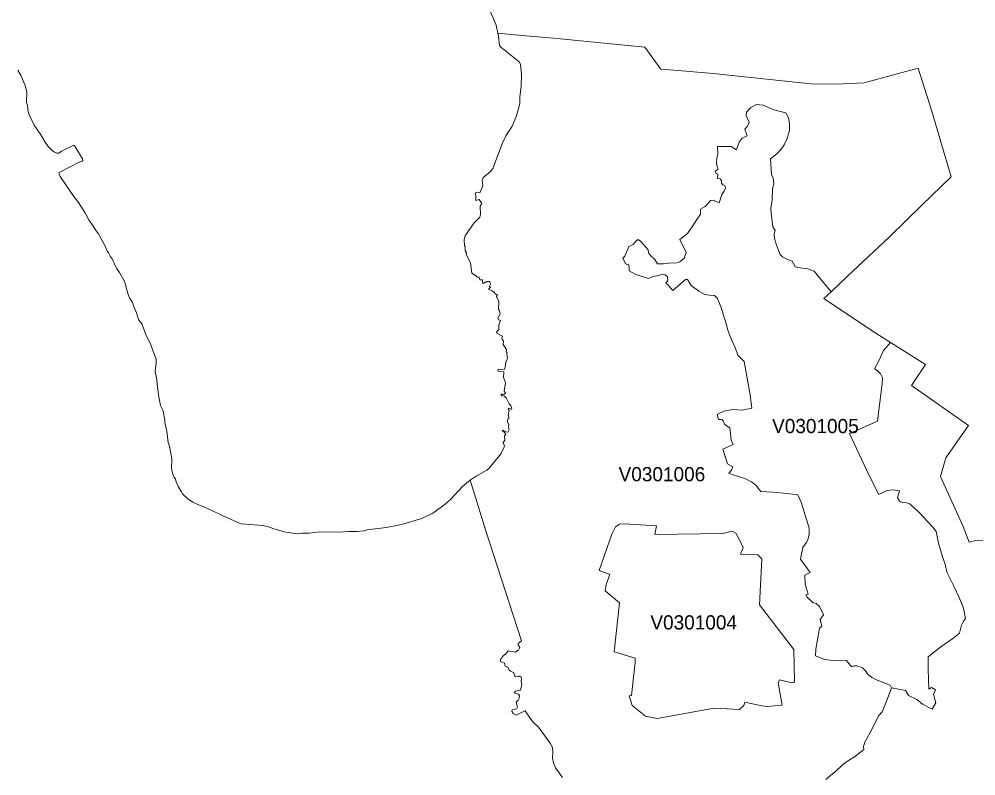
# Model space of a CAD drawing. Extents: x 369010 to 735936, y 6377141 to 6616555.
# Drawn here: x 386574 to 393307, y 6474944 to 6480269 of the extents above; entities that cross this region are included whole.
import ezdxf
from ezdxf.enums import TextEntityAlignment as Align

# ---------------------------------------------------------------- set-up
doc = ezdxf.new("R2010")
doc.units = 0
doc.header["$LTSCALE"] = 40
doc.layers.add('3', color=7, linetype='Continuous', lineweight=13)
doc.layers.add('4', color=7, linetype='Continuous')

msp = doc.modelspace()

# ---------------------------------------------------------------- linework, layer by layer
at = {"layer": '3'}
for points in [[(389891.85, 6480320.15), (389931.24, 6480224.99), (389943.15, 6480170.37)], [(391869.12, 6479176.02), (391880.87, 6479150.37), (391886.17, 6479106.84), (391876.9, 6479076.56), (391874.42, 6478996.29), (391865.15, 6478937.04), (391866.47, 6478905.42), (391878.22, 6478806.78), (391894.11, 6478780.47), (391888.49, 6478754.98), (391891.13, 6478724.69), (391904.37, 6478678.68), (391929.37, 6478612.81), (391946.41, 6478597.09), (391982, 6478577.23), (392014.77, 6478565.48), (392022.71, 6478548.27), (392035.78, 6478527.25), (392053, 6478521.95), (392124, 6478511.52), (392168.68, 6478494.31), (392188.54, 6478472.8), (392288.51, 6478350.82), (392402.05, 6478456.91), (392698.63, 6478737.44), (392926.36, 6478958.72), (393134.4, 6479159.8), (392995.38, 6479628.35), (392900.71, 6479924.6), (392788.99, 6479891.99), (392521.37, 6479819.34), (392325.91, 6479809.9), (392148.33, 6479812.72), (391678.13, 6479863.03), (391460, 6479886.37), (391182.61, 6479910.36), (391088.94, 6479917.15), (390978.21, 6480072.39), (390524.73, 6480116.75), (390410.04, 6480128.5), (390333.91, 6480135.45), (390140.76, 6480150.01), (390037.16, 6480161.1), (389943.15, 6480170.37), (389947.95, 6480147.7), (389953.58, 6480083.15), (389962.85, 6480071.57), (390092.6, 6479968.79), (390102.86, 6479951.08), (390110.48, 6479879.75), (390107.83, 6479796.5), (390096.57, 6479720.2), (390098.56, 6479674.36), (390074.4, 6479587.3), (390044.11, 6479514.64), (389999.09, 6479447.12), (389972.78, 6479391.18), (389907.73, 6479217.56), (389889.86, 6479194.06), (389840.04, 6479154.18), (389832.76, 6479134.32), (389836.73, 6479094.76), (389816.87, 6479047.43), (389800.16, 6479051.4), (389782.61, 6479045.11), (389788.24, 6479028.06), (389788.24, 6478993.64), (389810.75, 6478998.6), (389830.78, 6478971.63), (389818.86, 6478953.42), (389821.18, 6478894), (389815.22, 6478876.13), (389775.33, 6478836.57), (389712.94, 6478744.06), (389705.65, 6478717.74), (389707.97, 6478672.73), (389713.27, 6478669.25), (389712.61, 6478638.47), (389723.2, 6478623.24), (389719.56, 6478612.65), (389751.5, 6478553.89), (389760.77, 6478480.41), (389791.55, 6478460.88), (389795.85, 6478453.27), (389811.91, 6478452.6), (389817.2, 6478434.07), (389833.75, 6478435.06), (389835.74, 6478414.04), (389842.36, 6478407.75), (389852.95, 6478418.01), (389863.21, 6478417.02), (389867.52, 6478423.64), (389886.88, 6478422.81), (389890.19, 6478402.79), (389885.23, 6478389.88), (389891.18, 6478381.6), (389878.94, 6478373.66), (389877.94, 6478367.7), (389902.11, 6478357.94), (389911.71, 6478348.01)], [(389943.15, 6480170.37), (390037.16, 6480161.1), (390140.76, 6480150.01), (390333.91, 6480135.45), (390410.04, 6480128.5), (390524.73, 6480116.75), (390978.21, 6480072.39), (391088.94, 6479917.15), (391182.61, 6479910.36), (391460, 6479886.37), (391678.13, 6479863.03), (392148.33, 6479812.72), (392325.91, 6479809.9), (392521.37, 6479819.34), (392788.99, 6479891.99), (392900.71, 6479924.6), (392995.38, 6479628.35), (393134.4, 6479159.8), (392926.36, 6478958.72), (392698.63, 6478737.44), (392402.05, 6478456.91), (392288.51, 6478350.82), (392236.38, 6478302.16), (392576.65, 6478075.59), (392705.74, 6477994.49), (392888.46, 6477879.63), (392952.01, 6477838.42), (392854.53, 6477689.8), (393256.54, 6477409.1), (393095.67, 6477183.19), (393059.59, 6477049.79), (393217.98, 6476700.08), (393261.01, 6476588.2), (393307.02, 6476599.95), (393819.92, 6476581.75)], [(387041.37, 6478899.96), (386991.06, 6478978.41), (386958.78, 6479020.12), (386861.3, 6479162.45), (386852.53, 6479184.13), (386854.52, 6479188.44), (386999.99, 6479265.06), (387017.87, 6479269.04), (387020.85, 6479273.34), (387019.19, 6479285.42), (386965.74, 6479374.96), (386960.44, 6479380.25), (386954.15, 6479380.25), (386871.89, 6479338.71), (386853.19, 6479325.47), (386837.97, 6479326.47), (386823.07, 6479333.75), (386801.89, 6479349.14), (386777.23, 6479372.64), (386757.53, 6479401.94), (386726.75, 6479455.23), (386679.41, 6479523.25), (386650.12, 6479581.84), (386641.51, 6479603.35), (386637.87, 6479619.74), (386632.91, 6479661.78), (386626.95, 6479674.69), (386625.29, 6479682.96), (386628.27, 6479758.27), (386616.69, 6479801.79), (386585.08, 6479874.45), (386565.22, 6479910.7)], [(391631.46, 6477904.62), (391615.57, 6477950.63), (391578.83, 6478034.87), (391559.13, 6478086.18), (391553.18, 6478116.8), (391536.13, 6478169.43), (391516.27, 6478233.81), (391488.79, 6478303.65), (391467.61, 6478324.67), (391429.54, 6478327.32), (391393.96, 6478333.94), (391357.22, 6478354.96), (391303.26, 6478394.51), (391276.95, 6478436.55), (391262.55, 6478436.55), (391174.5, 6478360.25), (391125.68, 6478415.53), (391140.24, 6478427.28), (391137.76, 6478454.43), (391120.71, 6478470.31), (391103.5, 6478474.29), (391073.38, 6478465.02), (391036.47, 6478458.4), (390999.73, 6478444), (390910.19, 6478474.29), (390866.83, 6478497.95), (390868.15, 6478520.3), (390865.51, 6478539.99), (390841.84, 6478546.61), (390822.14, 6478587.49), (390836.54, 6478601.89), (390865.51, 6478669.08), (390895.79, 6478682.16), (390918.14, 6478711.12), (390931.21, 6478717.74), (390947.93, 6478705.83), (391000.56, 6478646.58), (391003.21, 6478624.23), (391017.6, 6478604.54), (391047.89, 6478578.06), (391067.59, 6478547.94), (391108.47, 6478547.94), (391163.58, 6478554.39), (391192.54, 6478551.74), (391222.83, 6478561.01), (391254.44, 6478587.33), (391267.52, 6478625.56), (391222.83, 6478717.58), (391278.11, 6478761.1), (391316.17, 6478815.06), (391343.81, 6478858.42), (391370.13, 6478896.65), (391370.13, 6478930.91), (391401.57, 6478949.28), (391416.97, 6478965.34), (391439.31, 6478991.65), (391461.65, 6478994.3), (391501.04, 6478975.93), (391519.41, 6479033.85), (391536.62, 6479057.52), (391545.73, 6479079.87), (391540.43, 6479097.08), (391527.36, 6479102.21), (391516.76, 6479114.12), (391518.09, 6479132.5), (391507.66, 6479145.74), (391487.97, 6479147.06), (391490.45, 6479177.35), (391476.05, 6479185.13), (391473.4, 6479198.37), (391493.1, 6479212.43), (391486.48, 6479232.13), (391482.5, 6479258.44), (391485.15, 6479290.06), (391490.45, 6479321.67), (391489.13, 6479371.65), (391585.12, 6479372.97), (391623.18, 6479347.98), (391641.55, 6479401.94), (391662.74, 6479432.22), (391698.16, 6479447.95), (391681.11, 6479494.12), (391699.48, 6479516.46), (391712.72, 6479544.1), (391690.21, 6479587.47), (391692.86, 6479613.78), (391720.5, 6479644.07), (391762.54, 6479669.06), (391810.04, 6479662.6), (391884.85, 6479630.99), (391969.09, 6479609.97), (391987.46, 6479573.07), (391995.4, 6479534.84), (391995.4, 6479482.21), (391975.71, 6479424.28), (391958.49, 6479384.89), (391936.15, 6479354.6), (391907.35, 6479320.84), (391862.67, 6479285.26), (391869.12, 6479176.02)], [(393144.83, 6475910.13), (393191.83, 6475948.03), (393206.23, 6476005.63), (393217.98, 6476029.3), (393233.7, 6476051.47), (393221.95, 6476113.04), (393216.66, 6476136.54), (393190.84, 6476198.94), (393155.58, 6476274.74), (393103.29, 6476378.18), (393090.21, 6476433.13), (393071.84, 6476485.42), (393044.37, 6476580.92), (393028.48, 6476663.01), (393004.81, 6476694.62), (392908.65, 6476797.23), (392841.62, 6476859.13), (392822.09, 6476866.41), (392789.32, 6476867.74), (392772.11, 6476874.36), (392756.39, 6476900.67), (392770.79, 6476949.33), (392726.1, 6476957.28), (392681.42, 6476951.98), (392623.65, 6476923.02), (392555.14, 6477062.54), (392418.6, 6477354.15), (392614.55, 6477439.72), (392648.98, 6477706.18), (392650.3, 6477744.25), (392635.74, 6477773.21), (392612.07, 6477796.88), (392595.02, 6477807.47), (392627.96, 6477874.66), (392656.92, 6477937.39), (392705.74, 6477994.49), (392576.65, 6478075.59), (392236.38, 6478302.16), (392288.51, 6478350.82), (392188.54, 6478472.8), (392168.68, 6478494.31), (392124, 6478511.52), (392053, 6478521.95), (392035.78, 6478527.25), (392022.71, 6478548.27), (392014.77, 6478565.48), (391982, 6478577.23), (391946.41, 6478597.09), (391929.37, 6478612.81), (391904.37, 6478678.68), (391891.13, 6478724.69), (391888.49, 6478754.98), (391894.11, 6478780.47), (391878.22, 6478806.78), (391866.47, 6478905.42), (391865.15, 6478937.04), (391874.42, 6478996.29), (391876.9, 6479076.56), (391886.17, 6479106.84), (391880.87, 6479150.37), (391869.12, 6479176.02), (391862.67, 6479285.26), (391907.35, 6479320.84), (391936.15, 6479354.6), (391958.49, 6479384.89), (391975.71, 6479424.28), (391995.4, 6479482.21), (391995.4, 6479534.84), (391987.46, 6479573.07), (391969.09, 6479609.97), (391884.85, 6479630.99), (391810.04, 6479662.6), (391762.54, 6479669.06), (391720.5, 6479644.07), (391692.86, 6479613.78), (391690.21, 6479587.47), (391712.72, 6479544.1), (391699.48, 6479516.46), (391681.11, 6479494.12), (391698.16, 6479447.95), (391662.74, 6479432.22), (391641.55, 6479401.94), (391623.18, 6479347.98), (391585.12, 6479372.97), (391489.13, 6479371.65), (391490.45, 6479321.67), (391485.15, 6479290.06), (391482.5, 6479258.44), (391486.48, 6479232.13), (391493.1, 6479212.43), (391473.4, 6479198.37), (391476.05, 6479185.13), (391490.45, 6479177.35), (391487.97, 6479147.06), (391507.66, 6479145.74), (391518.09, 6479132.5), (391516.76, 6479114.12), (391527.36, 6479102.21), (391540.43, 6479097.08), (391545.73, 6479079.87)], [(391545.73, 6479079.87), (391536.62, 6479057.52), (391519.41, 6479033.85), (391501.04, 6478975.93), (391461.65, 6478994.3), (391439.31, 6478991.65), (391416.97, 6478965.34), (391401.57, 6478949.28), (391370.13, 6478930.91), (391370.13, 6478896.65), (391343.81, 6478858.42), (391316.17, 6478815.06), (391278.11, 6478761.1), (391222.83, 6478717.58), (391267.52, 6478625.56), (391254.44, 6478587.33), (391222.83, 6478561.01), (391192.54, 6478551.74), (391163.58, 6478554.39), (391108.47, 6478547.94), (391067.59, 6478547.94), (391047.89, 6478578.06), (391017.6, 6478604.54), (391003.21, 6478624.23), (391000.56, 6478646.58), (390947.93, 6478705.83), (390931.21, 6478717.74), (390918.14, 6478711.12), (390895.79, 6478682.16), (390865.51, 6478669.08), (390836.54, 6478601.89), (390822.14, 6478587.49), (390841.84, 6478546.61), (390865.51, 6478539.99), (390868.15, 6478520.3), (390866.83, 6478497.95), (390910.19, 6478474.29), (390999.73, 6478444), (391036.47, 6478458.4), (391073.38, 6478465.02)], [(390096.74, 6475847.24), (390086.31, 6475865.61), (390086.31, 6475874.71), (390108.49, 6475894.41), (389857.75, 6476668.47), (389748.02, 6477024.64), (389735.78, 6477016.2), (389695.06, 6476979.62), (389611.98, 6476891.41), (389568.95, 6476854.17), (389484.54, 6476792.1), (389407.91, 6476754.86), (389265.25, 6476711.83), (389156.02, 6476692.14), (389022.12, 6476676.09), (388999.61, 6476668.8), (388954.1, 6476664.67), (388892.86, 6476663.51), (388821.86, 6476658.05), (388685.98, 6476660.53), (388615.15, 6476652.09), (388563.35, 6476650.93), (388531.57, 6476647.29), (388451.8, 6476659.2), (388367.22, 6476682.71), (388328, 6476697.6), (388289.6, 6476706.7), (388137.34, 6476716.8), (388086.86, 6476737.65), (388035.88, 6476762.64), (388006.92, 6476774.56), (387977.79, 6476790.45), (387952.8, 6476800.71), (387934.26, 6476809.32), (387868.89, 6476838.61), (387847.04, 6476845.56), (387796.23, 6476870.06), (387762.31, 6476891.41), (387724.41, 6476929.14), (387715.8, 6476943.04), (387694.28, 6476975.98), (387691.64, 6476989.22), (387679.06, 6477011.4), (387673.1, 6477033.24), (387664.66, 6477044.83), (387657.05, 6477061.21), (387648.44, 6477095.14), (387646.45, 6477108.71), (387647.45, 6477171.44), (387641.82, 6477217.61), (387629.24, 6477270.41), (387622.62, 6477290.27), (387613.35, 6477369.55), (387600.11, 6477429.62), (387598.62, 6477450.31), (387597.63, 6477455.94), (387591.01, 6477485.73), (387588.69, 6477503.44), (387583.07, 6477521.31), (387567.84, 6477551.1), (387559.89, 6477599.27), (387557.58, 6477612.51), (387554.76, 6477625.58), (387539.37, 6477743.92), (387530.6, 6477788.77), (387531.59, 6477794.06), (387538.05, 6477847.52), (387537.22, 6477871.19), (387534.9, 6477883.11), (387514.71, 6477936.56), (387499.15, 6477984.23), (387468.7, 6478043.15), (387438.75, 6478120.11), (387431.79, 6478132.69), (387426.17, 6478137.98), (387414.58, 6478155.86), (387399.52, 6478201.37), (387378.01, 6478252.18), (387370.39, 6478274.03), (387352.35, 6478302.99), (387343.08, 6478324.84), (387338.78, 6478339.4), (387337.46, 6478343.37), (387326.53, 6478378.96), (387321.24, 6478402.79), (387309.98, 6478432.41), (387280.03, 6478485.54), (387259.5, 6478516.99), (387255.2, 6478524.93), (387228.22, 6478581.37), (387214.98, 6478601.56), (387203.4, 6478623.57), (387194.13, 6478636.48), (387177.91, 6478670.74), (387131.07, 6478758.62), (387123.46, 6478768.88), (387110.22, 6478785.1), (387094.17, 6478813.07), (387065.04, 6478856.6), (387041.37, 6478899.96)], [(391073.38, 6478465.02), (391103.5, 6478474.29), (391120.71, 6478470.31), (391137.76, 6478454.43), (391140.24, 6478427.28), (391125.68, 6478415.53), (391174.5, 6478360.25), (391262.55, 6478436.55), (391276.95, 6478436.55), (391303.26, 6478394.51), (391357.22, 6478354.96), (391393.96, 6478333.94), (391429.54, 6478327.32), (391467.61, 6478324.67), (391488.79, 6478303.65), (391516.27, 6478233.81), (391536.13, 6478169.43), (391553.18, 6478116.8), (391559.13, 6478086.18), (391578.83, 6478034.87), (391615.57, 6477950.63), (391631.46, 6477904.62), (391677.47, 6477859.77), (391719.51, 6477624.26), (391731.26, 6477531.08), (391661.58, 6477518), (391595.88, 6477521.98), (391532.82, 6477511.38), (391485.48, 6477486.39), (391495.91, 6477452.46), (391518.25, 6477452.46), (391528.85, 6477442.04), (391539.27, 6477418.37), (391551.19, 6477406.45), (391576.18, 6477393.21), (391584.12, 6477305.17), (391599.85, 6477276.2), (391527.52, 6477243.27), (391559.13, 6477140.16), (391595.88, 6477119.14), (391586.77, 6477095.47), (391569.56, 6477074.45), (391591.9, 6477063.86), (391681.44, 6477037.55), (391728.77, 6477013.88), (391757.57, 6476990.21), (391793.16, 6476945.36), (391878.56, 6476941.39), (391978.52, 6476930.96), (392053.49, 6476921.69), (392077.16, 6476869.06), (392133.43, 6476687.84), (392133.43, 6476645.8), (392123.67, 6476604.42), (392117.21, 6476590.02), (392088.42, 6476550.8), (392072.69, 6476469.87), (392140.71, 6476375.7), (392104.14, 6476356.17), (392105.46, 6476293.27), (392127.64, 6476223.93), (392110.59, 6476217.47), (392120.85, 6476202.25), (392161.24, 6476163.02), (392182.26, 6476157.73), (392205.76, 6476136.87), (392235.88, 6476076.63), (392212.38, 6476044.03), (392224.13, 6475995.53), (392205.76, 6475983.78), (392180.93, 6475835.99), (392179.61, 6475789.15), (392242.33, 6475763), (392323.43, 6475753.73), (392397.91, 6475755.06), (392422.73, 6475723.94), (392437.13, 6475710.87), (392450.21, 6475717.49), (392468.58, 6475717.49), (392510.45, 6475704.41), (392526.01, 6475688.69), (392548.35, 6475657.24), (392574.5, 6475636.39), (392613.56, 6475617.02), (392705.08, 6475583.1), (392712.86, 6475564.73), (392812.99, 6475546.19), (392834.01, 6475510.77), (392892.76, 6475481.97), (392931.99, 6475448.05), (393000.01, 6475412.79), (393024.84, 6475457.15), (393009.11, 6475516.07), (393022.19, 6475550.16), (392996.04, 6475567.04), (392976.51, 6475555.29), (392971.21, 6475694.65), (392971.21, 6475782.36), (393060.09, 6475851.71), (393144.83, 6475910.13)], [(389911.71, 6478348.01), (389917.66, 6478349), (389921.97, 6478337.41), (389941.33, 6478326.49), (389932.56, 6478317.88), (389948.94, 6478281.31), (389946.63, 6478229.17), (389955.57, 6478215.93), (389958.21, 6478195.08), (389943.32, 6478163.8), (389946.3, 6478152.88), (389961.85, 6478147.25), (389948.94, 6478116.8), (389950.27, 6478087.17), (389934.55, 6478065.33), (389934.88, 6478058.04), (389975.43, 6478039.01), (389971.45, 6478019.81), (389983.04, 6478003.92), (389980.72, 6477978.6), (390004.06, 6477944.51), (390002.57, 6477928.95), (390007.37, 6477917.53), (390006.54, 6477907.6), (390010.35, 6477891.05), (390008.53, 6477876.49), (389997.93, 6477854.31), (389995.12, 6477821.7), (389988.67, 6477802.67), (389946.13, 6477805.32), (389941.83, 6477799.03), (389944.15, 6477792.41), (389984.2, 6477786.12), (389983.04, 6477747.39), (389996.61, 6477710.15), (389986.68, 6477651.4), (389995.95, 6477636.84), (389982.38, 6477625.58), (389968.47, 6477632.53), (389963.84, 6477629.55), (389971.12, 6477617.47), (389989.66, 6477614.82), (390001.08, 6477603.9), (390021.6, 6477562.36), (390034.18, 6477549.78), (390040.8, 6477531.24), (390039.31, 6477521.64), (390019.28, 6477530.58), (390016.64, 6477525.45), (390022.76, 6477516.02), (390016.64, 6477482.42), (390021.6, 6477461.24), (390013.33, 6477455.28), (390010.68, 6477434.26), (390019.95, 6477413.07), (390017.96, 6477396.85), (390022.59, 6477379.64), (390016.64, 6477365.91), (390011.34, 6477362.93), (389999.26, 6477365.08), (389978.9, 6477376.99), (389974.27, 6477374.35), (389989.66, 6477360.61), (389998.1, 6477347.04), (389989.33, 6477337.6), (389990.98, 6477306.16), (389980.72, 6477290.27), (389990.32, 6477264.45), (389966.82, 6477213.15), (389881.25, 6477109.54), (389865.2, 6477095.47), (389790.23, 6477053.6), (389748.02, 6477024.64)], [(393819.92, 6476581.75), (393307.02, 6476599.95), (393261.01, 6476588.2), (393217.98, 6476700.08), (393059.59, 6477049.79), (393095.67, 6477183.19), (393256.54, 6477409.1), (392854.53, 6477689.8), (392952.01, 6477838.42), (392888.46, 6477879.63), (392705.74, 6477994.49), (392656.92, 6477937.39), (392627.96, 6477874.66), (392595.02, 6477807.47), (392612.07, 6477796.88), (392635.74, 6477773.21), (392650.3, 6477744.25), (392648.98, 6477706.18), (392614.55, 6477439.72), (392418.6, 6477354.15), (392555.14, 6477062.54), (392623.65, 6476923.02), (392681.42, 6476951.98), (392726.1, 6476957.28), (392770.79, 6476949.33), (392756.39, 6476900.67), (392772.11, 6476874.36), (392789.32, 6476867.74), (392822.09, 6476866.41), (392841.62, 6476859.13), (392908.65, 6476797.23), (393004.81, 6476694.62), (393028.48, 6476663.01), (393044.37, 6476580.92), (393071.84, 6476485.42), (393090.21, 6476433.13), (393103.29, 6476378.18), (393155.58, 6476274.74), (393190.84, 6476198.94), (393216.66, 6476136.54), (393221.95, 6476113.04), (393233.7, 6476051.47), (393217.98, 6476029.3), (393206.23, 6476005.63), (393191.83, 6475948.03), (393144.83, 6475910.13), (393060.09, 6475851.71), (392971.21, 6475782.36), (392971.21, 6475694.65), (392976.51, 6475555.29), (392996.04, 6475567.04), (393022.19, 6475550.16), (393009.11, 6475516.07), (393024.84, 6475457.15), (393000.01, 6475412.79), (392931.99, 6475448.05), (392892.76, 6475481.97), (392834.01, 6475510.77), (392812.99, 6475546.19), (392712.86, 6475564.73), (392682.91, 6475482.3), (392647.49, 6475394.59), (392625.31, 6475368.44), (392604.46, 6475333.19), (392575.82, 6475269.63), (392526.17, 6475180.76), (392516.9, 6475151.96), (392519.55, 6475129.62), (392452.85, 6475078.64), (392424.22, 6475061.59), (392370.6, 6475025.02), (392314.33, 6474970.07), (392286.85, 6474950.37), (392250.94, 6474918.43)], [(392250.94, 6474918.43), (392286.85, 6474950.37), (392314.33, 6474970.07), (392370.6, 6475025.02), (392424.22, 6475061.59), (392452.85, 6475078.64), (392519.55, 6475129.62), (392516.9, 6475151.96), (392526.17, 6475180.76), (392575.82, 6475269.63), (392604.46, 6475333.19), (392625.31, 6475368.44), (392647.49, 6475394.59), (392682.91, 6475482.3), (392712.86, 6475564.73), (392705.08, 6475583.1), (392613.56, 6475617.02), (392574.5, 6475636.39), (392548.35, 6475657.24), (392526.01, 6475688.69), (392510.45, 6475704.41), (392468.58, 6475717.49), (392450.21, 6475717.49), (392437.13, 6475710.87), (392422.73, 6475723.94), (392397.91, 6475755.06), (392323.43, 6475753.73), (392242.33, 6475763), (392179.61, 6475789.15), (392180.93, 6475835.99), (392205.76, 6475983.78), (392224.13, 6475995.53), (392212.38, 6476044.03), (392235.88, 6476076.63), (392205.76, 6476136.87), (392182.26, 6476157.73), (392161.24, 6476163.02), (392120.85, 6476202.25), (392110.59, 6476217.47), (392127.64, 6476223.93), (392105.46, 6476293.27), (392104.14, 6476356.17), (392140.71, 6476375.7), (392072.69, 6476469.87), (392088.42, 6476550.8), (392117.21, 6476590.02), (392123.67, 6476604.42), (392133.43, 6476645.8), (392133.43, 6476687.84), (392077.16, 6476869.06), (392053.49, 6476921.69), (391978.52, 6476930.96), (391878.56, 6476941.39), (391793.16, 6476945.36), (391757.57, 6476990.21), (391728.77, 6477013.88), (391681.44, 6477037.55), (391591.9, 6477063.86), (391569.56, 6477074.45), (391586.77, 6477095.47), (391595.88, 6477119.14), (391559.13, 6477140.16), (391527.52, 6477243.27), (391599.85, 6477276.2), (391584.12, 6477305.17), (391576.18, 6477393.21), (391551.19, 6477406.45), (391539.27, 6477418.37), (391528.85, 6477442.04), (391518.25, 6477452.46), (391495.91, 6477452.46), (391485.48, 6477486.39), (391532.82, 6477511.38), (391595.88, 6477521.98), (391661.58, 6477518), (391731.26, 6477531.08), (391719.51, 6477624.26), (391677.47, 6477859.77), (391631.46, 6477904.62)], [(389748.02, 6477024.64), (389857.75, 6476668.47), (390108.49, 6475894.41), (390086.31, 6475874.71), (390086.31, 6475865.61), (390096.74, 6475847.24), (390088.96, 6475828.87), (390064.14, 6475814.47), (390015.64, 6475823.57), (389993.47, 6475797.42), (389981.71, 6475790.97), (389962.02, 6475763.33), (389959.37, 6475750.75), (389979.07, 6475742.97), (389990.82, 6475736.35), (389993.47, 6475716.82), (390014.32, 6475708.88), (390022.26, 6475688.03), (390032.69, 6475680.08), (390053.71, 6475670.98), (390065.46, 6475640.86), (390083.67, 6475645.99), (390096.91, 6475644.83), (390107.33, 6475639.53), (390109.98, 6475630.27), (390106.01, 6475610.74), (390111.14, 6475587.07), (390102.04, 6475547.84), (390066.78, 6475541.22), (390058.84, 6475529.47), (390088.96, 6475520.37), (390095.42, 6475506.47), (390094.09, 6475490.75), (390086.31, 6475476.35), (390071.91, 6475461.95), (390081.02, 6475427.85), (390075.89, 6475417.43), (390062.81, 6475412.13), (390044.44, 6475408.16), (390041.79, 6475399.06), (390052.22, 6475382.01), (390069.27, 6475371.58), (390134.64, 6475403.03), (390174.03, 6475342.78), (390194.88, 6475319.12), (390228.98, 6475287.67), (390273.33, 6475226.1), (390307.76, 6475177.78), (390328.61, 6475145.01), (390329.94, 6475112.4), (390327.29, 6475069.21), (390333.91, 6475036.44), (390349.46, 6474999.86), (390375.45, 6474965.44), (390397.63, 6474933.66)], [(390397.63, 6474933.66), (390375.45, 6474965.44), (390349.46, 6474999.86), (390333.91, 6475036.44), (390327.29, 6475069.21), (390329.94, 6475112.4), (390328.61, 6475145.01), (390307.76, 6475177.78), (390273.33, 6475226.1), (390228.98, 6475287.67), (390194.88, 6475319.12), (390174.03, 6475342.78), (390134.64, 6475403.03), (390069.27, 6475371.58), (390052.22, 6475382.01), (390041.79, 6475399.06), (390044.44, 6475408.16), (390062.81, 6475412.13), (390075.89, 6475417.43), (390081.02, 6475427.85), (390071.91, 6475461.95), (390086.31, 6475476.35), (390094.09, 6475490.75), (390095.42, 6475506.47), (390088.96, 6475520.37), (390058.84, 6475529.47), (390066.78, 6475541.22), (390102.04, 6475547.84), (390111.14, 6475587.07), (390106.01, 6475610.74), (390109.98, 6475630.27), (390107.33, 6475639.53), (390096.91, 6475644.83), (390083.67, 6475645.99), (390065.46, 6475640.86), (390053.71, 6475670.98), (390032.69, 6475680.08), (390022.26, 6475688.03), (390014.32, 6475708.88), (389993.47, 6475716.82), (389990.82, 6475736.35), (389979.07, 6475742.97), (389959.37, 6475750.75), (389962.02, 6475763.33), (389981.71, 6475790.97), (389993.47, 6475797.42), (390015.64, 6475823.57), (390064.14, 6475814.47), (390088.96, 6475828.87), (390096.74, 6475847.24)]]:
    msp.add_lwpolyline(points, dxfattribs=at)
for points in [[(391636.26, 6476619.65), (391618.88, 6476652.42), (391591.9, 6476665.82), (391525.87, 6476649.44), (391046.73, 6476641.83), (391060.14, 6476703.39), (390835.38, 6476718.29), (390797.98, 6476715.31), (390771, 6476695.78), (390744.69, 6476644.31), (390657.14, 6476389.1), (390730.29, 6476362.29), (390704.14, 6476290.3), (390699.01, 6476245.77), (390798.31, 6476160.71), (390761.57, 6475815.96), (390909.36, 6475771.44), (390909.36, 6475741.32), (390883.05, 6475509.12), (390867.49, 6475507.79), (390888.35, 6475439.77), (390981.19, 6475363.97), (391064.77, 6475348.25), (391465.62, 6475421.56), (391644.37, 6475411.14), (391673.17, 6475439.94), (391682.27, 6475463.6), (391801.27, 6475436.13), (391836.52, 6475433.48), (391943.76, 6475441.26), (391916.29, 6475599.65), (391925.39, 6475620.5), (392012.78, 6475598.32), (392027.18, 6475600.81), (392029.83, 6475608.75), (392025.85, 6475833.84), (391785.38, 6476148.62), (391799.78, 6476472.35), (391772.3, 6476498.5), (391650.66, 6476503.13), (391669.03, 6476550.3)], [(391636.26, 6476619.65), (391669.03, 6476550.3), (391650.66, 6476503.13), (391772.3, 6476498.5), (391799.78, 6476472.35), (391785.38, 6476148.62), (392025.85, 6475833.84), (392029.83, 6475608.75), (392027.18, 6475600.81), (392012.78, 6475598.32), (391925.39, 6475620.5), (391916.29, 6475599.65), (391943.76, 6475441.26), (391836.52, 6475433.48), (391801.27, 6475436.13), (391682.27, 6475463.6), (391673.17, 6475439.94), (391644.37, 6475411.14), (391465.62, 6475421.56), (391064.77, 6475348.25), (390981.19, 6475363.97), (390888.35, 6475439.77), (390867.49, 6475507.79), (390883.05, 6475509.12), (390909.36, 6475741.32), (390909.36, 6475771.44), (390761.57, 6475815.96), (390798.31, 6476160.71), (390699.01, 6476245.77), (390704.14, 6476290.3), (390730.29, 6476362.29), (390657.14, 6476389.1), (390744.69, 6476644.31), (390771, 6476695.78), (390797.98, 6476715.31), (390835.38, 6476718.29), (391060.14, 6476703.39), (391046.73, 6476641.83), (391525.87, 6476649.44), (391591.9, 6476665.82), (391618.88, 6476652.42)]]:
    msp.add_lwpolyline(points, close=True, dxfattribs=at)

# ---------------------------------------------------------------- texts
at = {"layer": '4'}
for s, p in [('V0301005', (392178.07, 6477355.62)), ('V0301006', (391097.71, 6477017.03)), ('V0301004', (391321.3, 6475974.28))]:
    msp.add_text(s, height=100, dxfattribs=at).set_placement(p, align=Align.CENTER)

doc.saveas('drawing.dxf')
